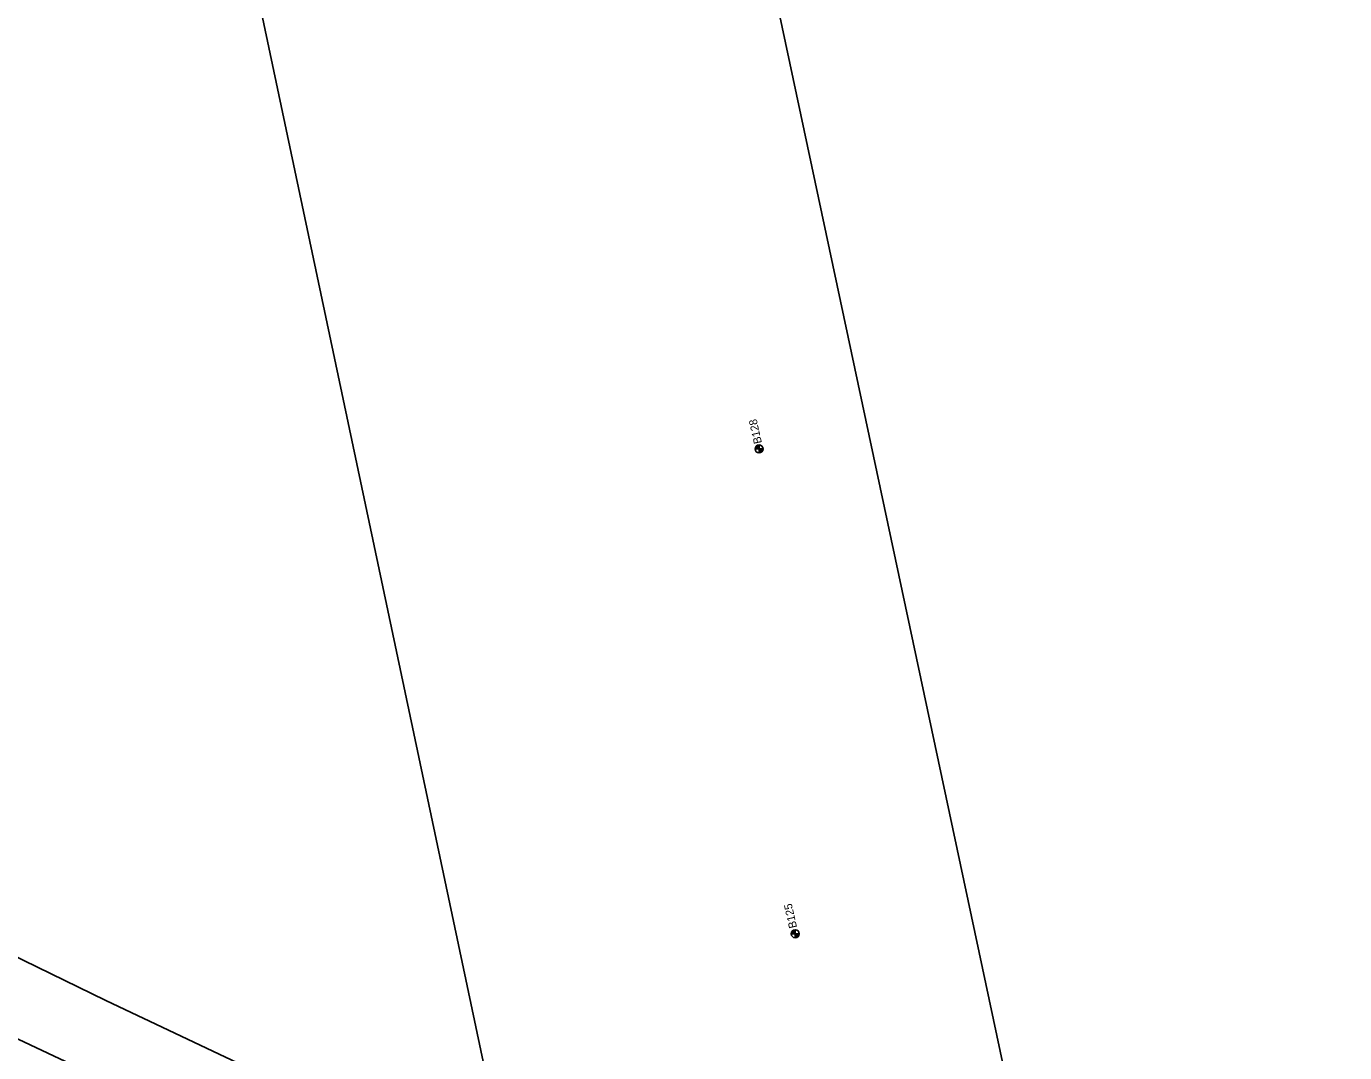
# Model space of a CAD drawing. Extents: x 345549 to 379569, y 127949 to 230467.
# Drawn here: x 355404 to 357051, y 198147 to 199429 of the extents above; entities that cross this region are included whole.
import ezdxf

# ---------------------------------------------------------------- set-up
doc = ezdxf.new("R2010")
doc.units = 0
for name, color, linetype in [('E_SOIL_BORE1 [KAPUR_CADDS_LEVELS]', 7, 'Continuous'), ('Level 1', 7, 'Continuous'), ('Level 58', 7, 'Continuous'), ('P_MARK', 7, 'Continuous'), ('P_TC', 7, 'Continuous')]:
    doc.layers.add(name, color=color, linetype=linetype)

msp = doc.modelspace()

# ---------------------------------------------------------------- linework, layer by layer
at = {"layer": 'Level 1'}
msp.add_lwpolyline([(357676.4, 197173.6), (357010.1, 197498.4), (355503, 198212.1), (353093.4, 199387.4)], dxfattribs=at)
at = {"layer": 'Level 58'}
msp.add_lwpolyline([(357613.2, 197099.2), (355794.7, 197965.7), (355489.7, 198118.4), (355097.3, 198303.2), (354592.9, 198551.6), (354237.9, 198717.3), (353050.1, 199302.6)], dxfattribs=at)
at = {"layer": 'P_MARK'}
for p, q in [((356314.3, 198901.3), (356324.3, 198901.3)), ((356319.3, 198906.3), (356319.3, 198896.3)), ((356364.4, 198300.4), (356364.4, 198290.4)), ((356359.4, 198295.4), (356369.4, 198295.4))]:
    msp.add_line(p, q, dxfattribs=at)
for centre in [(356319.3, 198901.3), (356364.4, 198295.4)]:
    msp.add_circle(centre, 5, dxfattribs=at)
for centre, radius, start, end in [((356319.3, 198901.3), 4.5, 89.9869, 179.9869), ((356319.3, 198901.3), 4, 89.9869, 179.9869), ((356319.3, 198901.3), 3.5, 89.9869, 179.9869), ((356319.3, 198901.3), 3, 89.9869, 179.9869), ((356319.3, 198901.3), 2.5, 89.9869, 179.9869), ((356319.3, 198901.3), 2, 89.9869, 179.9869), ((356319.3, 198901.3), 1.5, 89.9869, 179.9869), ((356319.3, 198901.3), 1, 89.9869, 179.9869), ((356319.3, 198901.3), 0.5, 89.9869, 179.9869), ((356319.3, 198901.3), 4.5, 269.9869, 359.9869), ((356319.3, 198901.3), 4, 269.9869, 359.9869), ((356319.3, 198901.3), 3.5, 269.9869, 359.9869), ((356319.3, 198901.3), 3, 269.9869, 359.9869), ((356319.3, 198901.3), 2.5, 269.9869, 359.9869), ((356319.3, 198901.3), 2, 269.9869, 359.9869), ((356319.3, 198901.3), 1.5, 269.9869, 359.9869), ((356319.3, 198901.3), 1, 269.9869, 359.9869), ((356319.3, 198901.3), 0.5, 269.9869, 359.9869), ((356364.4, 198295.4), 4.5, 89.9869, 179.9869), ((356364.4, 198295.4), 4, 89.9869, 179.9869), ((356364.4, 198295.4), 3.5, 89.9869, 179.9869), ((356364.4, 198295.4), 3, 89.9869, 179.9869), ((356364.4, 198295.4), 2.5, 89.9869, 179.9869), ((356364.4, 198295.4), 2, 89.9869, 179.9869), ((356364.4, 198295.4), 1.5, 89.9869, 179.9869), ((356364.4, 198295.4), 1, 89.9869, 179.9869), ((356364.4, 198295.4), 0.5, 89.9869, 179.9869), ((356364.4, 198295.4), 4.5, 269.9869, 359.9869), ((356364.4, 198295.4), 4, 269.9869, 359.9869), ((356364.4, 198295.4), 3.5, 269.9869, 359.9869), ((356364.4, 198295.4), 3, 269.9869, 359.9869), ((356364.4, 198295.4), 2.5, 269.9869, 359.9869), ((356364.4, 198295.4), 2, 269.9869, 359.9869), ((356364.4, 198295.4), 1.5, 269.9869, 359.9869), ((356364.4, 198295.4), 1, 269.9869, 359.9869), ((356364.4, 198295.4), 0.5, 269.9869, 359.9869)]:
    msp.add_arc(centre, radius, start, end, dxfattribs=at)
at = {"layer": 'P_TC'}
msp.add_lwpolyline([(356858.4, 196659.7), (356825.6, 197186.3), (356212, 200068.7), (355590.4, 199953.2), (356152.8, 197292.2), (356212, 196743)], dxfattribs=at)

# ---------------------------------------------------------------- texts
at = {"layer": 'E_SOIL_BORE1 [KAPUR_CADDS_LEVELS]'}
for s, p in [('B128', (356322.9, 198908.9)), ('B125', (356366.8, 198303.5))]:
    msp.add_text(s, height=10, rotation=102.6348, dxfattribs=at).set_placement(p)

doc.saveas('drawing.dxf')
